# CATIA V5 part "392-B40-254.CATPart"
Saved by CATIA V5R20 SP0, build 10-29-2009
Part number: 392-B40-254
Definition: NONE
Nomenclature: 392-B40-254
Source: Unknown
Description: 392-B40-254
Bounding box of the stored display mesh (mm): x 0 to 254, y -18.885 to 18.885, z -18.75 to 18.559
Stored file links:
  C:\Users\Utente\Desktop\IO LAVORO\3D X SITO CF\X SITO\3D files 392B\392-B40-254.CATPart
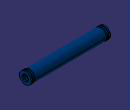
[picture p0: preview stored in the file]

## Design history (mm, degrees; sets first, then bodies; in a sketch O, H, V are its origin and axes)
Body1 "392-B40-254" (main body)
  Solid1: solid without history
